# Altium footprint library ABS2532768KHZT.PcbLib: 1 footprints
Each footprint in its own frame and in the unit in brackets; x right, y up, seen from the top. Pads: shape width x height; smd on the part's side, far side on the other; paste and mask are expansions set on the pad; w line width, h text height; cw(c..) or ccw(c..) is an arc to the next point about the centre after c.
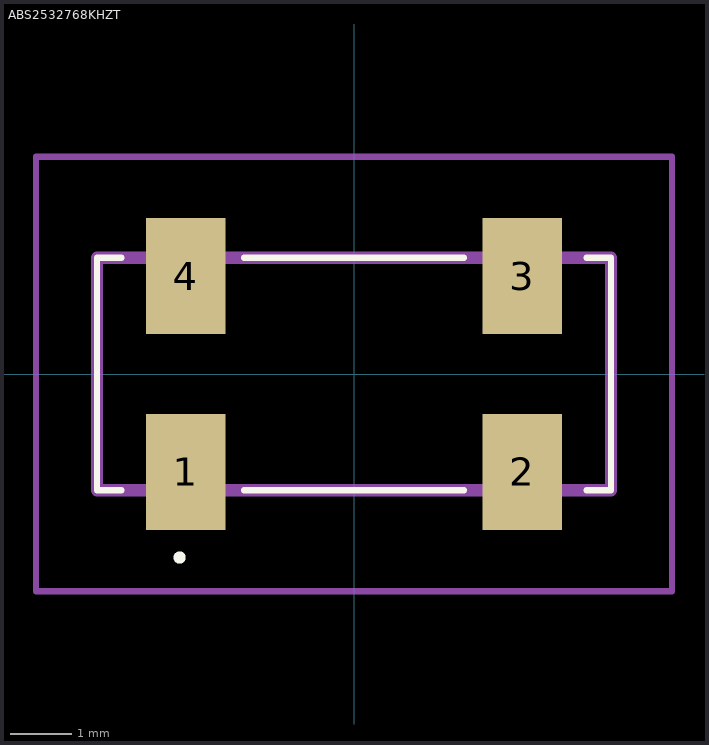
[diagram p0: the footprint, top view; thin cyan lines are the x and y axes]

## ABS2532768KHZT [mm]
pads (4):
  rect 1.3x1.9 smd: 1(-2.75,-1.6) 2(2.75,-1.6) 3(2.75,1.6) 4(-2.75,1.6)
Top Overlay:
  lines w0.1: -3.8,-1.9 -4.2,-1.9 -4.2,1.9 -3.8,1.9 ; -1.8,-1.9 1.8,-1.9 ; -1.8,1.9 1.8,1.9 ; 3.8,-1.9 4,-1.9 4.2,-1.9 4.2,1.9 3.8,1.9 ; -2.9,-3 cw(c-2.85,-3) -2.8,-3 ; -2.9,-3 -2.9,-3 ; -2.9,-3 ccw(c-2.85,-3) -2.8,-3 ; -2.8,-3 -2.8,-3
Mechanical 15:
  lines w0.2: -4.2,-1.9 4.2,-1.9 4.2,1.9 -4.2,1.9 -4.2,-1.9
Mechanical 20:
  lines w0.1: -5.2,-3.55 5.2,-3.55 5.2,3.55 -5.2,3.55 -5.2,-3.55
